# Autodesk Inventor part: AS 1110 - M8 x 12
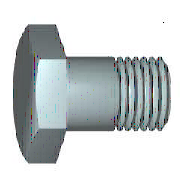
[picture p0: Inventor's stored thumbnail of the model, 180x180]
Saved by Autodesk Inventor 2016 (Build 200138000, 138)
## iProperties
IsCustomPart: 0
Created: 2015-02
Part Number: AS 1110 - M8 x 12
Material: Steel, Mild
Description: ISO metric hexagon precision bolts and screws
Document SubType Name: Modeling
Standard: AS 1110
Designer: stank
Standards Organization: AS
Language: en-US
Size Designation: M8 x 12
Categories: <MemberInstance><Categories><Category DisplayName="Fasteners" InternalName="e4da775c-781d-43d5-af7c-5136215cf5a6" Mnemonic="FSTN"><Category DisplayName="Bolts"
Density: 7.85 g/cm^3
Appearance: Semi-Polished
Author: stank
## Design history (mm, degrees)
sketch "Sketch1"
  geometry: L1 (0, 6.5)-(0, 4); L2 (3.7, 4)-(12, 4); L3 (12, 4)-(12, 0); L4 (12, 0)-(-0.6, 0); L5 (-0.7, 0)-(2.45, 0) reference; L6 (-0.6, 0)-(-0.6, 6.5); L7 (-0.6, 6.5)-(0, 6.5); L8 (3.7, 4)-(2.933, 4); L9 (2.933, 4)-(0, 4); L10 (0, -0.227)-(0, 1.362) reference
  constraints: 16 end point, 2 collinear, 2 perpendicular, 1 parallel
  dimensions: "d0" = 12 distance between parallel lines of L3 L1 (= NLG); "d1" = 8.3 distance from line of L2.start L3 (= GEL); "d2" = 8 diameter of L2 L4 (= GD); "d9" = 0.6001 distance between parallel lines of L6 L1 (computed from SD); "d10" = 13 diameter of L7 L4 (= SD2); "d13" = 0.76691 distance of L2.start L8.end (computed from GAL); "d14" = 8 diameter of L9 L4 (= BDM)
revolve "Body" sketch "Sketch1" stored, may be unused: angle "d12" = 90 deg
sketch "Sketch2"
  geometry: L1 (0, 7.506)-(6.5, 3.753); L2 (6.5, 3.753)-(6.5, -3.753); L3 (6.5, -3.753)-(0, -7.506); L4 (0, -7.506)-(-6.5, -3.753); L5 (-6.5, -3.753)-(-6.5, 3.753); L6 (-6.5, 3.753)-(0, 7.506); 2 further points
  constraints: 12 end point, 1 coincident, 1 vertical, 11 other
  dimensions: "d11" = 13 distance between parallel lines of L5 L2 (= SW)
extrude "Head" join sketch "Sketch2" distance "d3" = 4.7 (= KOH - SD); taper "d4" = 0 deg
sketch "Sketch4"
  geometry: L1 (-5.3, 6.5)-(-5.3, 7.506); L2 (-5.3, 7.506)-(-4.72, 7.506); L3 (-4.72, 7.506)-(-5.3, 6.5); L4 (-1.27, 0)-(-0.08, 0) reference; L5 (-0.6, 7.506)-(-5.3, 7.506) reference; L6 (-5.3, 3.753)-(-5.3, 7.506) reference
  constraints: 6 end point, 2 collinear, 1 perpendicular, 1 vertical
  dimensions: "d5" = 30 deg angle of L3 L1 (= ANG1); "d19" = 13 diameter of L1.start L4 (= SW0)
revolve "Chamfer1" sketch "Sketch4" stored, may be unused: angle "d21" = 90 deg
workplane "Work Plane1"
body "Solid1"
feature "Thread" dims "d15" = 8.3 (= GEL), "d16" = 0
chamfer "Chamfer2" distance "d6" = 0.76681 (= -0.5 x SPD + 0.5 x GD); stored, may be unused: second distance "d7" = 0.76691 (computed from GUL), angle "d55" = 45 deg
other parameters: "NLG" = 12 [user parameter; used in 1 equation term], "GD" = 8 (= NND) [user parameter; used in 2 equation terms], "BDM" = 8 (= NND) [user parameter; used in 1 equation term], "KOH" = 5.3 [user parameter; used in 1 equation term], "GEL" = 8.3 [user parameter; used in 2 equation terms], "SW" = 13 [user parameter; used in 5 equation terms], "SW0" = 13 (= SW) [user parameter; used in 1 equation term], "SPD" = 6.46637 (= NND - 1.2269 x PTC) [user parameter; used in 1 equation term], "SD2" = 13 (= SW) [user parameter; used in 1 equation term], "SD" = 0.6 [user parameter; used in 3 equation terms], "ANG1" = 30 deg [user parameter; used in 1 equation term], "GAL" = 0.76681 (= 0.61345 x PTC) [user parameter; used in 1 equation term], "GUL" = 0.76681 (= 0.61345 x PTC) [user parameter; used in 1 equation term], "d8" = 0, "RR" = 0.4 [user parameter], "d57" = 0, "d58" = 0, "TPU" = 8 (computed from PTC) [user parameter], "WFT" = 0.6 (= SD) [user parameter], "GD1" = 6.46637 (= THREADDIA - 1.2269 x PTC) [user parameter], "THREADDIA" = 8 [user parameter; used in 1 equation term], "SDH" = 13 (= SW) [user parameter], "TOA" = 30 deg [user parameter], "FAWI" = 45 deg [user parameter], "PTC" = 1.25 [user parameter; used in 5 equation terms], "NND" = 8 [user parameter; used in 3 equation terms], "E0" = 15.015 (= 1.155 x SW) [user parameter]
